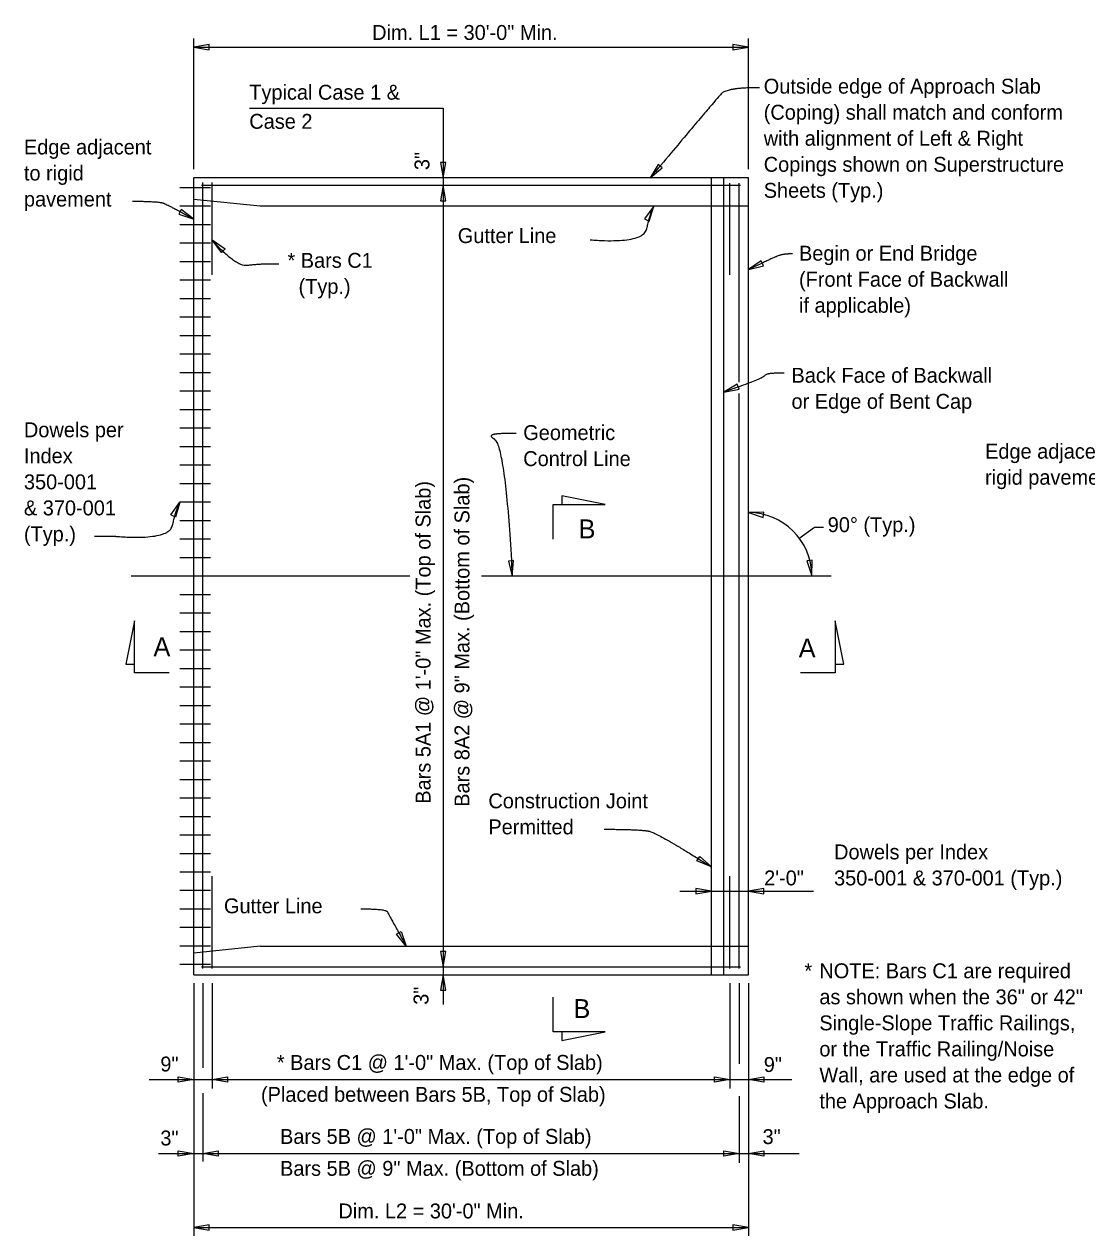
# Model space of a CAD drawing. Extents: x 0 to 153, y 2 to 105.
# Drawn here: x 0.4 to 57.9, y 37.9 to 103.4 of the extents above; entities that cross this region are included whole.
import ezdxf

# ---------------------------------------------------------------- set-up
doc = ezdxf.new("R2010")
doc.units = 0
for name, color, linetype in [('AppSlabConc', 7, 'Continuous'), ('AppSlabConc_h', 7, 'Continuous'), ('Dimension', 7, 'Continuous'), ('Rebar', 7, 'Continuous'), ('Rebar_h', 7, 'Continuous'), ('Symbols', 7, 'Continuous'), ('TextStructures', 7, 'Continuous')]:
    doc.layers.add(name, color=color, linetype=linetype)

msp = doc.modelspace()

# ---------------------------------------------------------------- linework, layer by layer
at = {"layer": 'AppSlabConc'}
for p, q in [((9.559, 51.991), (9.559, 95.074)), ((39.559, 95.074), (9.559, 95.074)), ((39.559, 51.991), (39.559, 95.074)), ((39.559, 51.991), (39.559, 93.808)), ((9.559, 51.991), (39.559, 51.991))]:
    msp.add_line(p, q, dxfattribs=at)
at = {"layer": 'AppSlabConc_h'}
for p, q in [((37.559, 51.991), (37.559, 95.074)), ((38.225, 51.991), (38.225, 95.074)), ((13.149, 93.533), (9.559, 93.91)), ((37.559, 93.533), (13.149, 93.533)), ((39.559, 93.533), (37.559, 93.533)), ((13.149, 53.533), (9.559, 53.156)), ((13.149, 53.533), (39.559, 53.533))]:
    msp.add_line(p, q, dxfattribs=at)
at = {"layer": 'Dimension'}
for p, q in [((9.559, 95.534), (9.559, 102.599)), ((39.559, 95.534), (39.559, 102.599)), ((9.559, 102.139), (39.559, 102.139)), ((12.574, 98.84), (23.053, 98.84)), ((23.053, 98.84), (23.053, 50.386)), ((5.356, 75.689), (4.189, 75.689)), ((21.242, 73.533), (6.172, 73.533)), ((44.035, 73.533), (25.127, 73.533)), ((35.858, 56.501), (43.081, 56.501)), ((9.559, 51.528), (9.559, 37.874)), ((10.059, 51.528), (10.059, 46.957)), ((10.559, 51.528), (10.559, 45.838)), ((38.559, 51.528), (38.559, 45.838)), ((39.059, 51.528), (39.059, 47.162)), ((39.559, 51.528), (39.559, 37.874)), ((7.156, 46.324), (41.903, 46.324)), ((10.059, 45.587), (10.059, 41.889)), ((39.059, 45.427), (39.059, 41.82)), ((7.656, 42.324), (42.312, 42.324)), ((9.559, 38.324), (39.559, 38.324))]:
    msp.add_line(p, q, dxfattribs=at)
for points in [[(9.559, 102.139), (10.392, 101.998), (10.392, 102.28)], [(39.559, 102.139), (38.726, 102.28), (38.726, 101.998)], [(23.053, 95.074), (23.194, 95.907), (22.912, 95.907)], [(34.252, 95.074), (34.901, 95.616), (34.687, 95.799)], [(23.053, 94.658), (22.912, 93.825), (23.194, 93.825)], [(9.559, 92.844), (8.888, 93.358), (8.756, 93.109)], [(34.439, 93.533), (33.941, 92.851), (34.193, 92.724)], [(11.061, 91.039), (10.559, 91.718), (11.257, 91.242)], [(39.559, 90.11), (40.376, 90.324), (40.26, 90.581)], [(38.225, 83.489), (39.055, 83.647), (38.957, 83.912)], [(8.32, 76.844), (8.809, 77.533), (8.574, 76.721)], [(39.559, 76.972), (40.363, 76.714), (40.403, 76.993)], [(26.791, 73.533), (26.864, 74.375), (26.582, 74.351)], [(42.997, 73.563), (43.007, 74.408), (42.728, 74.364)], [(36.93, 58.382), (37.559, 57.817), (36.779, 58.143)], [(37.559, 56.501), (36.726, 56.642), (36.726, 56.36)], [(39.559, 56.501), (40.392, 56.36), (40.392, 56.642)], [(20.774, 54.328), (21.059, 53.533), (20.528, 54.19)], [(23.053, 52.408), (23.194, 53.241), (22.912, 53.241)], [(23.053, 51.991), (22.912, 51.158), (23.194, 51.158)], [(9.559, 46.324), (8.726, 46.183), (8.726, 46.466)], [(10.559, 46.324), (11.392, 46.466), (11.392, 46.183)], [(38.559, 46.324), (37.726, 46.183), (37.726, 46.466)], [(39.559, 46.324), (40.392, 46.466), (40.392, 46.183)], [(9.559, 42.324), (8.726, 42.183), (8.726, 42.466)], [(10.059, 42.324), (10.892, 42.466), (10.892, 42.183)], [(39.059, 42.324), (38.226, 42.183), (38.226, 42.466)], [(39.559, 42.324), (40.392, 42.466), (40.392, 42.183)], [(9.559, 38.324), (10.392, 38.183), (10.392, 38.466)], [(39.559, 38.324), (38.726, 38.466), (38.726, 38.183)]]:
    msp.add_lwpolyline(points, close=True, dxfattribs=at)
msp.add_lwpolyline([(42.292, 75.571), (43.128, 76.18), (43.628, 76.18)], dxfattribs=at)
msp.add_arc((39.559, 73.533), 3.439, 0.50798, 90, dxfattribs=at)
for points in [[(40.157, 99.946), (38.422, 99.946), (37.805, 99.32), (34.252, 95.074)], [(6.253, 93.806), (7.632, 93.811), (8.204, 93.6), (9.559, 92.844)], [(31.003, 91.723), (33.887, 91.499), (34.243, 93.145), (34.439, 93.533)], [(14.167, 90.408), (13.141, 90.427), (11.846, 90.237), (10.559, 91.718)], [(41.949, 90.963), (41.449, 90.963), (40.882, 90.744), (39.559, 90.11)], [(41.493, 84.518), (40.488, 84.52), (40.4, 84.236), (38.225, 83.489)], [(26.993, 81.242), (25.181, 81.292), (26.414, 80.655), (26.791, 73.533)], [(5.356, 75.689), (8.241, 75.466), (8.597, 77.112), (8.809, 77.533)], [(31.752, 59.852), (33.737, 59.853), (34.693, 59.628), (37.559, 57.817)], [(18.594, 55.548), (19.973, 55.554), (20.113, 55.219), (21.059, 53.533)]]:
    msp.add_open_spline(points, degree=2, dxfattribs=at)
at = {"layer": 'Rebar'}
for p, q in [((9.559, 94.533), (8.809, 94.533)), ((39.142, 94.658), (9.975, 94.658)), ((10.059, 52.324), (10.059, 94.824)), ((10.559, 89.824), (10.559, 94.824)), ((38.559, 89.824), (38.559, 94.779)), ((39.059, 84.111), (39.059, 94.779)), ((9.559, 93.533), (8.809, 93.533)), ((9.559, 92.533), (8.809, 92.533)), ((9.559, 91.533), (8.809, 91.533)), ((9.559, 90.533), (8.809, 90.533)), ((9.559, 89.533), (8.809, 89.533)), ((9.559, 88.533), (8.809, 88.533)), ((9.559, 87.533), (8.809, 87.533)), ((9.559, 86.533), (8.809, 86.533)), ((9.559, 85.533), (8.809, 85.533)), ((9.559, 84.533), (8.809, 84.533)), ((39.059, 84.034), (39.059, 84.218)), ((9.559, 83.533), (8.809, 83.533)), ((39.059, 52.324), (39.059, 83.41)), ((9.559, 82.533), (8.809, 82.533)), ((9.559, 81.533), (8.809, 81.533)), ((9.559, 80.533), (8.809, 80.533)), ((9.559, 79.533), (8.809, 79.533)), ((9.559, 78.533), (8.809, 78.533)), ((9.559, 77.533), (8.809, 77.533)), ((9.559, 76.533), (8.809, 76.533)), ((9.559, 75.533), (8.809, 75.533)), ((9.559, 74.533), (8.809, 74.533)), ((9.559, 73.533), (8.809, 73.533)), ((9.559, 72.533), (8.809, 72.533)), ((9.559, 71.533), (8.809, 71.533)), ((9.559, 70.533), (8.809, 70.533)), ((9.559, 69.533), (8.809, 69.533)), ((9.559, 68.533), (8.809, 68.533)), ((9.559, 67.533), (8.809, 67.533)), ((9.559, 66.533), (8.809, 66.533)), ((9.559, 65.533), (8.809, 65.533)), ((9.559, 64.533), (8.809, 64.533)), ((9.559, 63.533), (8.809, 63.533)), ((9.559, 62.533), (8.809, 62.533)), ((9.559, 61.533), (8.809, 61.533)), ((9.559, 60.533), (8.809, 60.533)), ((9.559, 59.533), (8.809, 59.533)), ((9.559, 58.533), (8.809, 58.533)), ((9.559, 57.533), (8.809, 57.533)), ((10.559, 52.324), (10.559, 57.324)), ((38.559, 52.324), (38.559, 57.324)), ((9.559, 56.533), (8.809, 56.533)), ((9.559, 55.533), (8.809, 55.533)), ((9.559, 54.533), (8.809, 54.533)), ((9.559, 53.533), (8.809, 53.533)), ((9.559, 52.533), (8.809, 52.533)), ((9.975, 52.408), (39.142, 52.408))]:
    msp.add_line(p, q, dxfattribs=at)
at = {"layer": 'Rebar_h'}
for p, q in [((10.475, 94.533), (9.6, 94.533)), ((10.475, 93.533), (9.6, 93.533)), ((10.475, 92.533), (9.6, 92.533)), ((10.475, 91.533), (9.6, 91.533)), ((10.475, 90.533), (9.6, 90.533)), ((10.475, 89.533), (9.6, 89.533)), ((10.475, 88.533), (9.6, 88.533)), ((10.475, 87.533), (9.6, 87.533)), ((10.475, 86.533), (9.6, 86.533)), ((10.475, 85.533), (9.6, 85.533)), ((10.475, 84.533), (9.6, 84.533)), ((10.475, 83.533), (9.6, 83.533)), ((10.475, 82.533), (9.6, 82.533)), ((10.475, 81.533), (9.6, 81.533)), ((10.475, 80.533), (9.6, 80.533)), ((10.475, 79.533), (9.6, 79.533)), ((10.475, 78.533), (9.6, 78.533)), ((10.475, 77.533), (9.6, 77.533)), ((10.475, 76.533), (9.6, 76.533)), ((10.475, 75.533), (9.6, 75.533)), ((10.475, 74.533), (9.6, 74.533)), ((10.475, 73.533), (9.6, 73.533)), ((10.475, 72.533), (9.6, 72.533)), ((10.475, 71.533), (9.6, 71.533)), ((10.475, 70.533), (9.6, 70.533)), ((10.475, 69.533), (9.6, 69.533)), ((10.475, 68.533), (9.6, 68.533)), ((10.475, 67.533), (9.6, 67.533)), ((10.475, 66.533), (9.6, 66.533)), ((10.475, 65.533), (9.6, 65.533)), ((10.475, 64.533), (9.6, 64.533)), ((10.475, 63.533), (9.6, 63.533)), ((10.475, 62.533), (9.6, 62.533)), ((10.475, 61.533), (9.6, 61.533)), ((10.475, 60.533), (9.6, 60.533)), ((10.475, 59.533), (9.6, 59.533)), ((10.475, 58.533), (9.6, 58.533)), ((10.475, 57.533), (9.6, 57.533)), ((10.475, 56.533), (9.6, 56.533)), ((10.475, 55.533), (9.6, 55.533)), ((10.475, 54.533), (9.6, 54.533)), ((10.475, 53.533), (9.6, 53.533)), ((10.475, 52.533), (9.6, 52.533))]:
    msp.add_line(p, q, dxfattribs=at)
at = {"layer": 'Symbols'}
for points in [[(29, 75.53), (29, 77.405), (29.469, 77.405)], [(8.233, 68.314), (6.358, 68.314), (6.358, 68.782)], [(44.247, 68.782), (44.247, 68.314), (42.372, 68.314)], [(29.469, 48.902), (29, 48.902), (29, 50.777)]]:
    msp.add_lwpolyline(points, dxfattribs=at)
for points in [[(31.813, 77.405), (29.469, 77.873), (29.469, 77.405)], [(6.358, 71.126), (5.889, 68.782), (6.358, 68.782)], [(44.247, 71.126), (44.247, 68.782), (44.716, 68.782)], [(31.813, 48.902), (29.469, 48.902), (29.469, 48.433)]]:
    msp.add_lwpolyline(points, close=True, dxfattribs=at)

# ---------------------------------------------------------------- texts
at = {"layer": 'Dimension'}
for s, height, p in [('Outside edge of Approach Slab', 0.8064, (40.39, 99.625)), ('(Coping) shall match and conform', 0.8064, (40.39, 98.217)), ('with alignment of Left & Right', 0.8064, (40.39, 96.809)), ('Edge adjacent', 0.8064, (0.378, 96.338)), ('to rigid ', 0.8064, (0.378, 94.93)), ('Copings shown on Superstructure', 0.8064, (40.39, 95.401)), ('Sheets (Typ.)', 0.8064, (40.39, 93.993)), ('pavement', 0.8064, (0.378, 93.522)), ('Begin or End Bridge', 0.8064, (42.298, 90.594)), ('* Bars C1', 0.8064, (14.632, 90.208)), ('(Front Face of Backwall', 0.8064, (42.298, 89.186)), ('  (Typ.)', 0.8064, (14.632, 88.8)), ('if applicable)', 0.8064, (42.298, 87.778)), ('Back Face of Backwall', 0.8064, (41.892, 83.994)), ('or Edge of Bent Cap', 0.8064, (41.892, 82.586)), ('Dowels per', 0.8064, (0.378, 81.048)), ('Geometric ', 0.8064, (27.383, 80.896)), ('Edge adjacent to ', 0.8064, (52.361, 79.888)), ('Index', 0.8064, (0.378, 79.64)), ('Control Line', 0.8064, (27.383, 79.488)), ('rigid pavement', 0.8064, (52.361, 78.48)), ('350-001', 0.8064, (0.378, 78.232)), ('& 370-001', 0.8064, (0.378, 76.824)), ('(Typ.)', 0.8064, (0.378, 75.416)), ('Construction Joint', 0.8064, (25.498, 60.986)), ('Permitted', 0.8064, (25.498, 59.578)), ('Dowels per Index', 0.8064, (44.195, 58.225)), ('350-001 & 370-001 (Typ.)', 0.8064, (44.195, 56.817)), ('*', 0.806, (42.591, 51.797)), ('NOTE: Bars C1 are required ', 0.8064, (43.398, 51.797)), ('as shown when the 36" or 42" ', 0.8064, (43.398, 50.389)), ('Single-Slope Traffic Railings, ', 0.8064, (43.398, 48.981)), ('or the Traffic Railing/Noise ', 0.8064, (43.398, 47.573)), ('Wall, are used at the edge of ', 0.8064, (43.398, 46.165)), ('the Approach Slab.', 0.8064, (43.398, 44.757))]:
    msp.add_text(s, height=height, dxfattribs=at).set_placement(p)
at = {"layer": 'TextStructures'}
for s, height, p in [('Dim. L1 = 30\'-0" Min.', 0.8064, (19.212, 102.529)), ('Typical Case 1 & ', 0.8064, (12.567, 99.299)), ('Case 2', 0.8064, (12.567, 97.725)), ('Gutter Line', 0.8064, (23.842, 91.546)), ('90° (Typ.)', 0.8064, (43.851, 75.918)), ('B', 1.024, (30.376, 75.581)), ('A', 1.024, (7.384, 69.211)), ('A', 1.024, (42.281, 69.141)), ('2\'-0"', 0.8064, (40.412, 56.818)), ('Gutter Line', 0.8064, (11.197, 55.309)), ('B', 1.024, (30.098, 49.646)), ('9"', 0.8064, (7.757, 46.757)), ('* Bars C1 @ 1\'-0" Max. (Top of Slab)', 0.8064, (14.057, 46.842)), ('9"', 0.8064, (40.393, 46.73)), ('(Placed between Bars 5B, Top of Slab) ', 0.8064, (13.199, 45.116)), ('3"', 0.8064, (7.757, 42.757)), ('Bars 5B @ 1\'-0" Max. (Top of Slab)', 0.8064, (14.231, 42.842)), ('3"', 0.8064, (40.327, 42.831)), ('Bars 5B @ 9" Max. (Bottom of Slab)', 0.8064, (14.231, 41.116)), ('Dim. L2 = 30\'-0" Min.', 0.8064, (17.387, 38.813))]:
    msp.add_text(s, height=height, dxfattribs=at).set_placement(p)
for s, p in [('3"', (22.31, 95.49)), ('Bars 5A1 @ 1\'-0" Max. (Top of Slab)', (22.37, 61.235)), ('Bars 8A2 @ 9" Max. (Bottom of Slab)', (24.473, 61.068)), ('3"', (22.26, 50.361))]:
    msp.add_text(s, height=0.8064, rotation=90, dxfattribs=at).set_placement(p)

doc.saveas('drawing.dxf')
